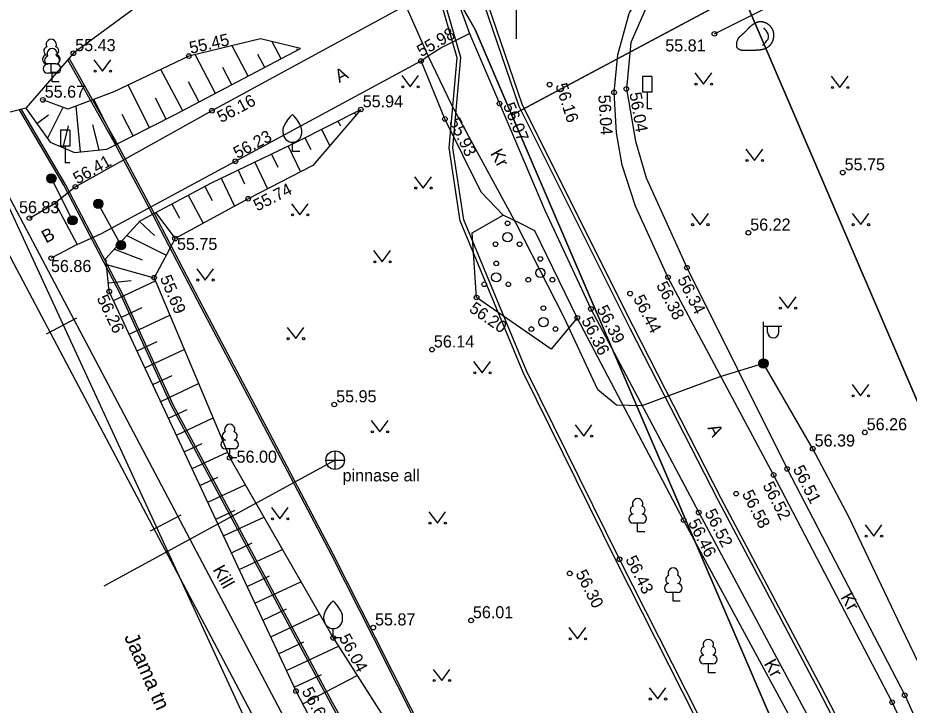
# Model space of a CAD drawing. Extents: x 542320 to 543602, y 6558748 to 6559969.
# Drawn here: x 542573.14 to 542621.18, y 6559312.11 to 6559349.12 of the extents above; entities that cross this region are included whole.
import ezdxf

# ---------------------------------------------------------------- set-up
doc = ezdxf.new("R2010")
doc.units = 0
for name, color, linetype in [('HALJASTUS', 7, 'Continuous'), ('KKAEV', 7, 'Continuous'), ('KORGUS-EH2000', 7, 'Continuous'), ('KPKAABEL', 7, 'Continuous'), ('KTRASS', 7, 'Continuous'), ('LIIKLUS', 7, 'Continuous'), ('mootpiir', 7, 'Continuous'), ('MPKAABEL', 7, 'Continuous'), ('PIIR', 7, 'Continuous'), ('POST', 7, 'Continuous'), ('PUU', 7, 'Continuous'), ('RDT', 7, 'Continuous'), ('RELJEEF', 7, 'Continuous'), ('SITRASS', 7, 'Continuous'), ('TEE', 7, 'Continuous'), ('VORK', 7, 'Continuous')]:
    doc.layers.add(name, color=color, linetype=linetype)

# ---------------------------------------------------------------- blocks, each defined once
blk = doc.blocks.new('VKORIS')
for p, q in [((0, 4), (0, -4)), ((-4, 0), (4, 0))]:
    blk.add_line(p, q)
blk = doc.blocks.new('VILJA1')
for p, q in [((0, 0), (0, 1)), ((0.8, 0), (0, 0))]:
    blk.add_line(p, q)
for points in [[(-1, 2), (-1, 2.3), (-0.98, 2.43), (-0.91, 2.69), (-0.79, 2.93), (-0.5, 3.4), (-0.18, 3.81), (0, 4)], [(1, 2), (1, 2.3), (0.98, 2.43), (0.91, 2.69), (0.79, 2.93), (0.5, 3.4), (0.18, 3.81), (0, 4)]]:
    blk.add_lwpolyline(points)
blk.add_arc((0, 2), 1, 180, 0)
blk = doc.blocks.new('LEHTP1')
for p, q in [((0.48, 0.95), (-0.48, 0.95)), ((0, 0), (0, 0.95)), ((0.76, 0), (0, 0))]:
    blk.add_line(p, q)
for centre, radius, start, end in [((0, 3.04), 0.554, 332.5799, 207.4201), ((-0.34, 2.345), 0.465, 109.02174, 253.14154), ((0.34, 2.345), 0.465, 286.85082, 70.98591), ((-0.475, 1.425), 0.475, 90.0016, 269.3953), ((0.475, 1.425), 0.475, 270.6047, 89.9984)]:
    blk.add_arc(centre, radius, start, end)
blk = doc.blocks.new('PQQSAS')
for centre, radius in [((0, 1.5), 0.25), ((0, 0), 0.5), ((-1.3, -0.75), 0.25), ((1.3, -0.75), 0.25)]:
    blk.add_circle(centre, radius)
blk = doc.blocks.new('MEPOST')
for radius in [0.5, 0.45, 0.4, 0.35, 0.3, 0.25, 0.2, 0.15, 0.1, 0.05]:
    blk.add_circle((0, 0), radius)
blk = doc.blocks.new('VAPOST')
for p, q in [((0, 0.5), (0, 4.5)), ((0, 4), (2, 4)), ((0.453, 3.358), (0.453, 4)), ((1.679, 3.358), (1.679, 4))]:
    blk.add_line(p, q)
blk.add_arc((1.066, 3.358), 0.613, 180, 0)
blk = doc.blocks.new('KIVISU')
blk.add_lwpolyline([(0.72, -0.83), (0.805, -0.74), (0.942, -0.594), (1.078, -0.447), (1.213, -0.299), (1.326, -0.136), (1.376, 0.057), (1.377, 0.257), (1.335, 0.452), (1.25, 0.632), (1.124, 0.788), (0.993, 0.938), (0.861, 1.089)])
blk.add_open_spline([(-2.05, -0.57), (-2.05, -0.57), (-2.04, -1.087), (-1.653, -1.345), (-1.153, -1.37), (-0.653, -1.371), (-0.153, -1.357), (0.345, -1.322), (0.84, -1.252), (1.292, -1.047), (1.643, -0.693), (1.87, -0.251), (1.94, 0.243), (1.881, 0.738), (1.666, 1.186), (1.306, 1.529), (0.853, 1.737), (0.359, 1.777), (-0.102, 1.588), (-0.509, 1.3), (-0.857, 0.942), (-1.203, 0.581), (-1.58, 0.254), (-1.944, -0.084), (-2.05, -0.57)], degree=2)
blk = doc.blocks.new('LIIKLM')
for points in [[(-0.5, 3.5), (-0.5, 1.8)], [(0.5, 3.5), (-0.5, 3.5)], [(0.5, 3.5), (0.5, 1.8)], [(0.5, 1.8), (-0.5, 1.8)], [(0, 1.8), (0, 0)], [(0.5, 0), (0, 0)]]:
    blk.add_lwpolyline(points)
blk = doc.blocks.new('MURU')
for p, q in [((-0.927, 1.213), (0, 0)), ((0, 0), (0.891, 1.213))]:
    blk.add_line(p, q)
for centre in [(-0.802, 0), (0.856, 0)]:
    blk.add_circle(centre, 0.11)
blk = doc.blocks.new('RING02')
blk.add_circle((0, 0), 0.25)
blk = doc.blocks.new('KAKAEV')
for p, q in [((0, -1), (0, 1)), ((-1, 0), (1, 0))]:
    blk.add_line(p, q)
blk.add_circle((0, 0), 1)

msp = doc.modelspace()

# ---------------------------------------------------------------- linework, layer by layer
at = {"layer": 'HALJASTUS'}
for points in [[(542610.682, 6559348.263), (542627.616, 6559356.728)], [(542603.292, 6559332.961), (542601.88, 6559331.279), (542597.861, 6559334.061), (542597.62, 6559337.542), (542599.29, 6559338.496)]]:
    msp.add_lwpolyline(points, dxfattribs=at)
at = {"layer": 'KPKAABEL'}
for points in [[(542592.521, 6559362.446), (542597.547, 6559351.945), (542600.14, 6559344.366), (542606.118, 6559332.403), (542610.857, 6559323.162), (542616.273, 6559312.944), (542622.065, 6559301.812), (542626.969, 6559292.384), (542631.614, 6559283.754), (542633.958, 6559279.16), (542635.835, 6559275.606), (542642.325, 6559262.55)], [(542592.701, 6559362.532), (542597.732, 6559352.021), (542600.325, 6559344.443), (542606.296, 6559332.493), (542611.034, 6559323.254), (542616.45, 6559313.037), (542622.242, 6559301.904), (542627.146, 6559292.478), (542631.791, 6559283.847), (542634.136, 6559279.252), (542636.013, 6559275.697), (542642.504, 6559262.639)], [(542629.705, 6559255.548), (542624.459, 6559265.014), (542621.333, 6559278.998), (542619.565, 6559289.352), (542615.605, 6559299.115), (542610.376, 6559310.033), (542605.393, 6559319.873), (542600.368, 6559330.022), (542596.984, 6559338.198), (542596.381, 6559342.121), (542596.809, 6559346.972), (542595.758, 6559350.645), (542591.144, 6559359.29), (542590.252, 6559360.802)], [(542629.88, 6559255.645), (542624.648, 6559265.086), (542621.529, 6559279.037), (542619.758, 6559289.407), (542615.788, 6559299.196), (542610.555, 6559310.121), (542605.572, 6559319.963), (542600.55, 6559330.105), (542597.178, 6559338.252), (542596.582, 6559342.128), (542597.011, 6559346.991), (542595.944, 6559350.72), (542591.318, 6559359.388), (542590.424, 6559360.904)]]:
    msp.add_lwpolyline(points, dxfattribs=at)
at = {"layer": 'KTRASS'}
msp.add_lwpolyline([(542590.238, 6559325.304), (542577.775, 6559318.513)], dxfattribs=at)
at = {"layer": 'LIIKLUS'}
for points in [[(542576.088, 6559338.218), (542574.943, 6559340.472)], [(542577.474, 6559339.108), (542578.694, 6559336.875)]]:
    msp.add_lwpolyline(points, dxfattribs=at)
at = {"layer": 'mootpiir'}
msp.add_lwpolyline([(542580.596, 6559350.501), (542576.13, 6559347.213), (542573.572, 6559344.253), (542570.527, 6559343.48), (542613.7, 6559249.972), (542615.953, 6559250.584), (542618.546, 6559251.554), (542622.286, 6559253.49), (542626.884, 6559255.347), (542629.88, 6559255.645), (542630.445, 6559256.8), (542630.818, 6559257.341), (542632.786, 6559258.084), (542634.681, 6559258.868), (542635.466, 6559259.163), (542639.905, 6559261.019), (542642.325, 6559262.55), (542647.794, 6559265.185), (542644.803, 6559292.129), (542641.558, 6559300.605), (542636.848, 6559320.338), (542627.616, 6559356.728)], dxfattribs=at)
at = {"layer": 'MPKAABEL'}
for points in [[(542623.663, 6559310.291), (542620.741, 6559316.319), (542617.922, 6559322.244), (542615.983, 6559325.919), (542613.321, 6559330.51), (542610.967, 6559329.797), (542606.767, 6559328.232), (542605.407, 6559328.268), (542604.389, 6559329.083), (542602.561, 6559333.02), (542600.004, 6559338.039), (542596.54, 6559344.378), (542595.26, 6559347.076), (542591.882, 6559354.707)], [(542622.093, 6559253.39), (542621.335, 6559255.374), (542617.705, 6559263.498), (542614.681, 6559269.795), (542611.089, 6559277.807), (542606.04, 6559289.597), (542605.819, 6559290.909), (542605.062, 6559292.013), (542601.327, 6559298.317), (542596.156, 6559308.103), (542592.302, 6559315.731), (542590.046, 6559320.195), (542585.68, 6559328.499), (542583.041, 6559333.495), (542580.391, 6559338.551), (542578.352, 6559342.398), (542575.831, 6559346.867)], [(542622.183, 6559253.436), (542621.427, 6559255.412), (542617.796, 6559263.54), (542614.772, 6559269.837), (542611.181, 6559277.847), (542606.137, 6559289.625), (542605.914, 6559290.947), (542605.146, 6559292.067), (542601.414, 6559298.366), (542596.245, 6559308.149), (542592.391, 6559315.776), (542590.135, 6559320.241), (542585.768, 6559328.546), (542583.129, 6559333.542), (542580.479, 6559338.598), (542578.44, 6559342.446), (542575.9, 6559346.947)]]:
    msp.add_lwpolyline(points, dxfattribs=at)
at = {"layer": 'PIIR'}
for points in [[(542456.68, 6559581.07), (542523.83, 6559477.46), (542537.52, 6559453.62), (542591.81, 6559358.92), (542597.79, 6559348.5), (542599.76, 6559343.89), (542619.08, 6559298.96), (542624.28, 6559266.08), (542637.46, 6559233.17), (542680, 6559143.81), (542700.43, 6559093.84), (542700.92, 6559090.29), (542704.02, 6559067.82)], [(542741.15, 6559419.37), (542715.89, 6559405.45), (542681.21, 6559386.88), (542667.3, 6559379.98), (542641.94, 6559366.51), (542632.02, 6559361.13), (542612.16, 6559350.51), (542599.76, 6559343.89), (542597.79, 6559348.5), (542591.81, 6559358.92), (542604.23, 6559363.42), (542605.82, 6559364.28), (542625.12, 6559374.24), (542659.87, 6559392.24), (542673.76, 6559400.37), (542691.07, 6559409.58), (542708.69, 6559418.93), (542715.22, 6559422.45), (542743.96, 6559437.79)], [(542632.63, 6559302.87), (542612.16, 6559350.51), (542632.02, 6559361.13), (542651.63, 6559324.28), (542646.33, 6559321.44), (542665.85, 6559284.72), (542671.39, 6559287.65), (542689.34, 6559253.48), (542704.9, 6559215.47), (542674.63, 6559203.23), (542672.45, 6559208.6), (542665.71, 6559205.86), (542632.63, 6559302.87)], [(542612.16, 6559350.51), (542632.63, 6559302.87), (542665.71, 6559205.86), (542667.87, 6559200.49), (542682.31, 6559164.31), (542683.94, 6559160.9), (542699.54, 6559124.27), (542718.47, 6559078.4), (542700.92, 6559090.29), (542700.43, 6559093.84), (542680, 6559143.81), (542637.46, 6559233.17), (542624.28, 6559266.08), (542619.08, 6559298.96), (542599.76, 6559343.89), (542612.16, 6559350.51)]]:
    msp.add_lwpolyline(points, dxfattribs=at)
at = {"layer": 'RDT'}
for points in [[(542570.527, 6559343.48), (542587.317, 6559311.762), (542594.415, 6559298.323), (542600.925, 6559284.44), (542609.327, 6559263.254), (542613.7, 6559249.972)], [(542569.237, 6559342.797), (542586.027, 6559311.079), (542593.108, 6559297.672), (542599.584, 6559283.86), (542607.954, 6559262.756), (542612.313, 6559249.515)], [(542574.674, 6559332.098), (542576.318, 6559332.968)], [(542580.288, 6559321.492), (542581.932, 6559322.362)]]:
    msp.add_lwpolyline(points, dxfattribs=at)
at = {"layer": 'RELJEEF'}
for points in [[(542588.379, 6559347.469), (542586.223, 6559347.985), (542582.354, 6559347.064), (542578.315, 6559345.133), (542575.824, 6559344.199), (542574.485, 6559344.704)], [(542587.329, 6559346.916), (542586.844, 6559347.836)], [(542573.572, 6559344.253), (542574.883, 6559342.422), (542576.197, 6559341.878), (542577.93, 6559342.049), (542581.624, 6559343.91), (542588.379, 6559347.469)], [(542585.559, 6559345.983), (542584.696, 6559347.622)], [(542588.214, 6559347.382), (542588.175, 6559347.454)], [(542583.79, 6559345.051), (542582.688, 6559347.143)], [(542586.444, 6559346.45), (542586.072, 6559347.155)], [(542582.021, 6559344.119), (542580.848, 6559346.344)], [(542584.675, 6559345.517), (542584.183, 6559346.45)], [(542580.238, 6559343.212), (542579.085, 6559345.501)], [(542582.905, 6559344.585), (542582.328, 6559345.68)], [(542581.131, 6559343.662), (542580.559, 6559344.797)], [(542576.521, 6559341.91), (542576.279, 6559344.369)], [(542578.452, 6559342.312), (542577.235, 6559344.728)], [(542574.154, 6559343.44), (542574.789, 6559343.895)], [(542574.736, 6559342.627), (542575.569, 6559344.273)], [(542611.276, 6559263.245), (542601.766, 6559284.942), (542595.436, 6559298.859), (542588.129, 6559312.865), (542578.066, 6559334.392), (542577.883, 6559336.16), (542579.736, 6559338.198), (542583.573, 6559340.233), (542588.18, 6559342.437), (542591.624, 6559344.187)], [(542579.345, 6559342.762), (542578.761, 6559343.922)], [(542591.624, 6559344.187), (542589.04, 6559341.17), (542585.552, 6559339.38), (542581.614, 6559337.235), (542580.482, 6559335.129), (542584.558, 6559325.434), (542590.137, 6559315.731), (542599.476, 6559301.09), (542603.506, 6559285.65), (542611.276, 6559263.245)], [(542591.281, 6559344.013), (542591.353, 6559343.871)], [(542577.516, 6559342.008), (542577.174, 6559343.355)], [(542590.39, 6559343.56), (542590.52, 6559343.305)], [(542575.574, 6559342.136), (542575.871, 6559343.302)], [(542589.498, 6559343.107), (542589.945, 6559342.227)], [(542588.607, 6559342.654), (542588.924, 6559342.03)], [(542587.71, 6559342.212), (542588.372, 6559340.827)], [(542586.808, 6559341.781), (542587.145, 6559341.076)], [(542585.906, 6559341.349), (542586.592, 6559339.914)], [(542584.101, 6559340.486), (542584.821, 6559338.982)], [(542585.004, 6559340.917), (542585.353, 6559340.187)], [(542583.207, 6559340.039), (542583.605, 6559339.288)], [(542582.324, 6559339.57), (542583.126, 6559338.058)], [(542581.44, 6559339.102), (542581.844, 6559338.341)], [(542580.557, 6559338.633), (542581.614, 6559337.235)], [(542579.688, 6559338.146), (542580.499, 6559337.408)], [(542579.016, 6559337.406), (542581.129, 6559336.348)], [(542578.343, 6559336.666), (542579.843, 6559336.092)], [(542577.916, 6559335.845), (542580.482, 6559335.129)], [(542578.019, 6559334.851), (542579.244, 6559334.977)], [(542578.294, 6559333.904), (542580.553, 6559334.96)], [(542578.718, 6559332.998), (542579.829, 6559333.517)], [(542579.141, 6559332.092), (542581.329, 6559333.115)], [(542579.565, 6559331.186), (542580.641, 6559331.689)], [(542579.988, 6559330.28), (542582.105, 6559331.269)], [(542580.412, 6559329.374), (542581.452, 6559329.861)], [(542580.835, 6559328.468), (542582.88, 6559329.424)], [(542581.259, 6559327.562), (542582.263, 6559328.032)], [(542581.682, 6559326.656), (542583.656, 6559327.579)], [(542582.106, 6559325.751), (542583.075, 6559326.204)], [(542582.529, 6559324.845), (542584.432, 6559325.734)], [(542582.952, 6559323.939), (542583.924, 6559324.393)], [(542583.376, 6559323.033), (542585.396, 6559323.977)], [(542583.799, 6559322.127), (542584.848, 6559322.617)], [(542584.223, 6559321.221), (542586.396, 6559322.237)], [(542584.646, 6559320.315), (542585.771, 6559320.841)], [(542585.07, 6559319.409), (542587.397, 6559320.497)], [(542585.493, 6559318.503), (542586.695, 6559319.065)], [(542585.917, 6559317.597), (542588.397, 6559318.757)], [(542586.34, 6559316.691), (542587.619, 6559317.289)], [(542586.764, 6559315.786), (542589.398, 6559317.017)], [(542587.187, 6559314.88), (542588.543, 6559315.513)], [(542587.611, 6559313.974), (542590.42, 6559315.287)], [(542588.034, 6559313.068), (542589.498, 6559313.752)], [(542588.488, 6559312.177), (542591.426, 6559313.71)]]:
    msp.add_lwpolyline(points, dxfattribs=at)
at = {"layer": 'SITRASS'}
for points in [[(542620.078, 6559252.347), (542619.611, 6559253.421), (542618.452, 6559255.17), (542617.973, 6559256.008), (542615.234, 6559262.86), (542599.652, 6559294.601), (542592.248, 6559308.146), (542591.915, 6559308.725), (542590.021, 6559312.164), (542581.41, 6559328.232), (542578.732, 6559334.135), (542575.622, 6559340.107), (542573.231, 6559344.166)], [(542620.167, 6559252.393), (542619.699, 6559253.469), (542618.919, 6559254.85), (542618.555, 6559255.685), (542618.063, 6559256.052), (542615.325, 6559262.901), (542599.741, 6559294.647), (542592.335, 6559308.195), (542592.292, 6559308.9), (542591.74, 6559309.316), (542590.109, 6559312.212), (542581.5, 6559328.276), (542578.822, 6559334.179), (542575.709, 6559340.156), (542573.331, 6559344.192)]]:
    msp.add_lwpolyline(points, dxfattribs=at)
at = {"layer": 'TEE'}
for points in [[(542624.102, 6559367.101), (542623.091, 6559366.625), (542619.655, 6559364.738), (542606.495, 6559357.531), (542598.927, 6559352.716), (542596.394, 6559351.262), (542597.483, 6559348.273), (542599.096, 6559344.51), (542601.523, 6559338.799), (542604.022, 6559333.449), (542609.839, 6559322.477), (542616.479, 6559310.106), (542621.369, 6559299.405), (542623.152, 6559294.601), (542623.728, 6559292.736), (542624.325, 6559289.249), (542624.923, 6559285.031), (542624.921, 6559280.093), (542625.11, 6559275.875), (542626.159, 6559270.713), (542630.818, 6559257.341)], [(542634.681, 6559258.868), (542630.146, 6559271.916), (542629.129, 6559276.409), (542628.98, 6559278.994), (542628.987, 6559283.205), (542628.787, 6559287.956), (542628.207, 6559291.798), (542627.216, 6559295.847), (542627.153, 6559296.256), (542626, 6559299.915), (542624.094, 6559304.138), (542620.263, 6559312.262), (542613.869, 6559324.503), (542608.179, 6559335.156), (542606.426, 6559338.985), (542605.717, 6559341.19), (542605.399, 6559342.931), (542605.274, 6559345.104), (542605.472, 6559347.122), (542606.079, 6559349.35), (542607.837, 6559352.387), (542608.749, 6559353.701), (542625.256, 6559362.999)], [(542625.586, 6559362.35), (542608.76, 6559352.379), (542607.276, 6559350.302), (542606.168, 6559347.789), (542605.934, 6559345.297), (542606.434, 6559342.484), (542606.994, 6559340.503), (542609.201, 6559335.669), (542614.601, 6559324.827), (542620.939, 6559312.64), (542624.605, 6559304.516), (542626.856, 6559298.567), (542627.692, 6559295.961), (542628.381, 6559292.605), (542629.031, 6559288.15), (542629.33, 6559283.803), (542629.221, 6559279.539), (542629.398, 6559276.511), (542629.819, 6559274.787), (542630.575, 6559272.193), (542635.466, 6559259.163)], [(542596.394, 6559351.262), (542594.538, 6559350.061), (542583.594, 6559344.119), (542576.237, 6559340.023), (542575.154, 6559339.138)], [(542576.326, 6559336.91), (542577.638, 6559337.511), (542584.861, 6559341.4), (542594.87, 6559346.799), (542595.26, 6559347.076), (542595.932, 6559347.511), (542597.483, 6559348.273)], [(542630.445, 6559256.8), (542625.172, 6559270.111), (542624.375, 6559274.673), (542623.873, 6559280.787), (542623.665, 6559288.876), (542622.433, 6559294.202), (542622.365, 6559295.059), (542620.97, 6559299.05), (542615.719, 6559309.698), (542609.023, 6559322.07), (542603.292, 6559332.961), (542601.008, 6559337.652), (542600.271, 6559338.024), (542599.29, 6559338.496), (542598.116, 6559339.729), (542596.153, 6559343.676), (542594.87, 6559346.799)], [(542573.762, 6559338.334), (542575.154, 6559339.138), (542576.326, 6559336.91), (542574.939, 6559336.179)]]:
    msp.add_lwpolyline(points, dxfattribs=at)

# ---------------------------------------------------------------- block references
at = {"layer": 'HALJASTUS', "xscale": 0.5, "yscale": 0.5}
for name, p in [('MURU', (542577.702, 6559346.248)), ('MURU', (542594.289, 6559345.413)), ('MURU', (542610.092, 6559345.548)), ('MURU', (542617.445, 6559345.369)), ('MURU', (542612.841, 6559341.442)), ('MURU', (542594.981, 6559339.956)), ('MURU', (542588.343, 6559338.508)), ('MURU', (542609.908, 6559337.984)), ('MURU', (542618.565, 6559337.985)), ('PQQSAS', (542599.532, 6559337.306)), ('MURU', (542592.778, 6559335.987)), ('PQQSAS', (542601.297, 6559335.39)), ('PQQSAS', (542598.923, 6559335.147)), ('MURU', (542583.241, 6559335.003)), ('MURU', (542614.634, 6559333.487)), ('PQQSAS', (542601.465, 6559332.736)), ('MURU', (542588.111, 6559331.845)), ('MURU', (542598.168, 6559330)), ('MURU', (542618.563, 6559328.769)), ('MURU', (542592.643, 6559326.823)), ('MURU', (542603.635, 6559326.591)), ('MURU', (542587.263, 6559322.142)), ('MURU', (542595.75, 6559321.91)), ('MURU', (542619.267, 6559321.208)), ('MURU', (542603.304, 6559315.681)), ('MURU', (542595.982, 6559313.429)), ('MURU', (542607.625, 6559312.439))]:
    msp.add_blockref(name, p, dxfattribs=at)
at = {"layer": 'KKAEV', "xscale": 0.5, "yscale": 0.5}
msp.add_blockref('KAKAEV', (542590.238, 6559325.304), dxfattribs=at)
at = {"layer": 'KORGUS-EH2000', "xscale": 0.5, "yscale": 0.5}
for p in [(542610.682, 6559348.263), (542576.13, 6559347.213), (542582.354, 6559347.064), (542594.87, 6559346.799), (542601.797, 6559345.526), (542605.934, 6559345.297), (542574.485, 6559344.704), (542605.274, 6559345.104), (542591.624, 6559344.187), (542599.096, 6559344.51), (542583.594, 6559344.119), (542596.153, 6559343.676), (542584.861, 6559341.4), (542617.598, 6559340.792), (542576.237, 6559340.023), (542585.552, 6559339.38), (542573.762, 6559338.334), (542612.511, 6559337.549), (542581.614, 6559337.235), (542574.939, 6559336.179), (542609.201, 6559335.669), (542580.482, 6559335.129), (542608.179, 6559335.156), (542578.066, 6559334.392), (542606.137, 6559334.273), (542597.861, 6559334.061), (542604.022, 6559333.449), (542603.292, 6559332.961), (542595.46, 6559331.253), (542590.193, 6559328.299), (542618.788, 6559326.795), (542615.983, 6559325.919), (542584.558, 6559325.434), (542613.869, 6559324.503), (542614.601, 6559324.827), (542611.853, 6559323.497), (542609.839, 6559322.477), (542609.023, 6559322.07), (542605.572, 6559319.963), (542602.883, 6559319.2), (542597.564, 6559316.67), (542592.29, 6559316.282), (542590.137, 6559315.731), (542588.129, 6559312.865), (542620.939, 6559312.64), (542620.263, 6559312.262)]:
    msp.add_blockref('RING02', p, dxfattribs=at)
at = {"layer": 'LIIKLUS', "xscale": 0.5, "yscale": 0.5}
for name, p in [('LIIKLM', (542607.06, 6559344.214)), ('LIIKLM', (542575.686, 6559341.316)), ('MEPOST', (542574.943, 6559340.472)), ('MEPOST', (542577.474, 6559339.108)), ('MEPOST', (542576.088, 6559338.218)), ('MEPOST', (542578.694, 6559336.875))]:
    msp.add_blockref(name, p, dxfattribs=at)
at = {"layer": 'POST', "xscale": 0.5, "yscale": 0.5}
for name in ['VAPOST', 'MEPOST']:
    msp.add_blockref(name, (542613.321, 6559330.51), dxfattribs=at)
at = {"layer": 'PUU', "xscale": 0.5, "yscale": 0.5}
for name, p in [('LEHTP1', (542574.937, 6559346.175)), ('LEHTP1', (542574.984, 6559345.672)), ('VILJA1', (542587.935, 6559341.923)), ('LEHTP1', (542584.558, 6559325.434)), ('LEHTP1', (542606.543, 6559321.435)), ('LEHTP1', (542608.46, 6559317.701)), ('VILJA1', (542590.137, 6559315.731)), ('LEHTP1', (542610.354, 6559313.851))]:
    msp.add_blockref(name, p, dxfattribs=at)
at = {"layer": 'RELJEEF', "xscale": 0.5, "yscale": 0.5}
msp.add_blockref('KIVISU', (542612.906, 6559348.044), dxfattribs=at)
at = {"layer": 'VORK', "xscale": 0.5, "yscale": 0.5}
msp.add_blockref('VKORIS', (542600, 6559350), dxfattribs=at)

# ---------------------------------------------------------------- texts
at = {"layer": 'KKAEV'}
msp.add_text('pinnase all', height=0.65, dxfattribs=at).set_placement((542590.641, 6559324.158))
at = {"layer": 'KORGUS-EH2000'}
for s, rotation, p in [('55.45', 12.6706, (542582.458, 6559347.181)), ('55.98', 29.6808, (542594.876, 6559346.997)), ('56.16', 287.8235, (542602.103, 6559345.492)), ('56.16', 27.8242, (542584.094, 6559343.449)), ('56.04', 273.5017, (542604.422, 6559344.96)), ('56.04', 279.6923, (542606.097, 6559345.065)), ('56.07', 292.3549, (542599.276, 6559344.407)), ('55.93', 295.8864, (542596.353, 6559343.546)), ('56.23', 27.9701, (542584.969, 6559341.519)), ('56.41', 29.359, (542576.345, 6559340.142)), ('55.74', 27.0009, (542586.041, 6559338.691)), ('55.69', 292.8672, (542580.782, 6559335.113)), ('56.34', 297.0695, (542608.665, 6559335.031)), ('56.38', 297.0695, (542607.53, 6559334.724)), ('56.26', 295.8196, (542577.373, 6559334.022)), ('56.44', 297.0695, (542606.286, 6559334.008)), ('56.20', 325.2244, (542597.413, 6559333.344)), ('56.39', 297.0695, (542604.315, 6559333.448)), ('56.36', 297.0695, (542603.495, 6559332.82)), ('56.51', 297.0695, (542614.894, 6559324.826)), ('56.52', 297.0695, (542613.265, 6559323.944)), ('56.58', 297.0695, (542612.146, 6559323.496)), ('56.52', 297.0695, (542610.132, 6559322.476)), ('56.46', 297.0695, (542609.246, 6559321.943)), ('56.43', 297.0695, (542605.865, 6559319.962)), ('56.30', 297.0695, (542603.176, 6559319.199)), ('56.04', 298.2389, (542590.428, 6559315.734)), ('56.68', 298.2389, (542588.42, 6559312.868))]:
    msp.add_text(s, height=0.65, rotation=rotation, dxfattribs=at).set_placement(p)
for s, p in [('55.43', (542576.23, 6559347.33)), ('55.81', (542608.032, 6559347.313)), ('55.67', (542574.585, 6559344.821)), ('55.94', (542591.724, 6559344.304)), ('55.75', (542617.698, 6559340.909)), ('56.83', (542573.199, 6559338.599)), ('56.22', (542612.611, 6559337.666)), ('55.75', (542581.713, 6559336.62)), ('56.86', (542574.921, 6559335.433)), ('56.14', (542595.56, 6559331.37)), ('55.95', (542590.293, 6559328.416)), ('56.26', (542618.888, 6559326.912)), ('56.39', (542616.083, 6559326.036)), ('56.00', (542584.926, 6559325.164)), ('56.01', (542597.664, 6559316.787)), ('55.87', (542592.39, 6559316.399))]:
    msp.add_text(s, height=0.65, dxfattribs=at).set_placement(p)
at = {"layer": 'PIIR'}
msp.add_text('Jaama tn 6 // Tallinna-Lelle-Pärnu 32,5-33,3 km', height=0.8, rotation=294.0027, dxfattribs=at).set_placement((542578.851, 6559315.781))
at = {"layer": 'TEE'}
for s, rotation, p in [('A', 28.2532, (542590.459, 6559345.605)), ('Kr', 299.4082, (542598.577, 6559341.822)), ('B', 28.2532, (542574.652, 6559336.966)), ('A', 296.2462, (542610.298, 6559327.043)), ('Kill', 299.4082, (542583.619, 6559319.409)), ('Kr', 299.4082, (542617.459, 6559317.926)), ('Kr', 299.4082, (542613.325, 6559314.347))]:
    msp.add_text(s, height=0.7, rotation=rotation, dxfattribs=at).set_placement(p)

doc.saveas('drawing.dxf')
